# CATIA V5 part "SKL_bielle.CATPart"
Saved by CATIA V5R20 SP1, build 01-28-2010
Part number: SKL_bielle
Bounding box of the stored display mesh (mm): x -50 to 0, y 0 to 0, z -50 to 50
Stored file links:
  C:\Users\Nikow\Documents\IAO\Mécanisme IAO avec squelette\nsarlin\SKL_bielle.CATPart
  J:\IAO\Mecanisme_a_bielle_et_deux_coulisseaux.CATProduct
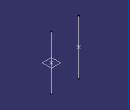
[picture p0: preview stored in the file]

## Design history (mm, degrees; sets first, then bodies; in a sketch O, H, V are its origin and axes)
Set1
  Point1 "Point_coulisseau1": linked copy from another document
  Point2 "Point_coulisseau2": linked copy from another document
  Plane1 "Plan_de_ref": linked copy from another document
Body1 (main body)
  Point3: (0, 0, 0), relative to Point1
  Point4 "Point.2": (0, 0, 0), relative to Point2
  Line1 "Pvt1": type Normal, RefPoint Point3, RefSkin Plane1, Start -50, End 50
  Line2 "Pvt2": type Normal, RefPoint Point4, RefSkin Plane1, Start -50, End 50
